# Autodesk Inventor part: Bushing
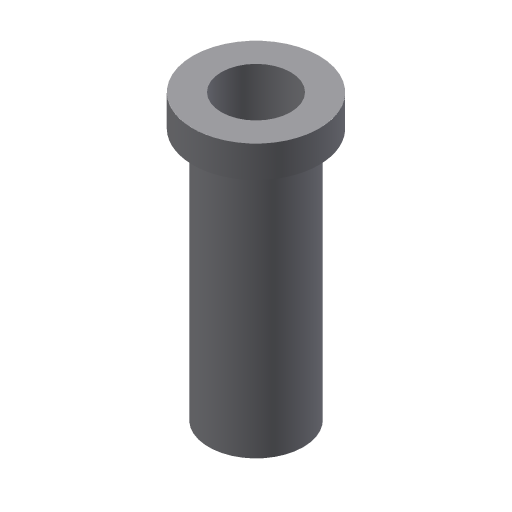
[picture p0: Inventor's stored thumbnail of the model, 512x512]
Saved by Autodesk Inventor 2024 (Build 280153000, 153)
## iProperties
Shininess: 77.0
Length Units: 11269
Angle Units: 11279
Time Units: 11290
Mass Units: 11283
Length Display Precision: 3
Angle Display Precision: 2
Created: 2002-02
Part Number: Bushing
Document SubType Name: Modeling
Designer: ***
Density: 1 g/cm^3
Material: Generic
Appearance: Default
Density: 0.0
Volumn: 0.0
Area: 0.0
PropertySet Name: Model Information
Control State: 0
Master: False
Checked Out: False
Author: ***
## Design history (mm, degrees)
sketch "Sketch2"
  geometry: C1 r 10 at (0, 0); 1 further point
  constraints: 1 centre point, 1 coincident
  dimensions: "d8" = 20 diameter of C1
extrude "Extrusion1" new body sketch "Sketch2" distance "d6" = 5; taper "d7" = 0 deg
sketch "Sketch4"
  geometry: C1 r 7.5 at (0, 0); 1 further point
  constraints: 1 centre point, 1 coincident
  dimensions: "d9" = 15 diameter of C1
extrude "Extrusion2" join sketch "Sketch4" distance "d10" = 40; taper "d11" = 0 deg
sketch "Sketch5"
  geometry: C1 r 5.5 at (0, 0); 1 further point
  constraints: 1 centre point, 1 coincident
  dimensions: "d12" = 11 diameter of C1
extrude "Extrusion3" cut sketch "Sketch5" distance "d13" = 57.75; taper "d14" = 0 deg
body "Solid2"
